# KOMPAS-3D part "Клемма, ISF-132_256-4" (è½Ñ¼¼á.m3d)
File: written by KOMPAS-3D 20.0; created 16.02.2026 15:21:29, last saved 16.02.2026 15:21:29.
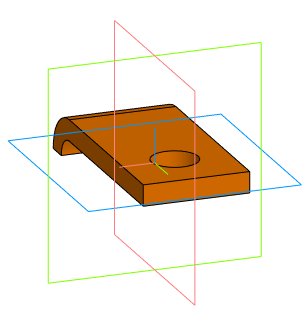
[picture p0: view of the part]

Document properties: Автор: admin; Полное имя файла: P:\INSTART\Технический отдел\ОР\Прочие задачи\КД на номенклатурный ряд\КД на типоразмеры дросселей\Сетевые дроссели ISF\ISF-4\Тип 1\ISF-132_256-4\0723\Новая папка\Клемма.m3d

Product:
- Part/product: Клемма  | designation ISF-132_256-4

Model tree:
1. Операция без истории:1

Expressions: ISF-132_256-4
